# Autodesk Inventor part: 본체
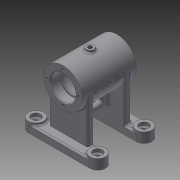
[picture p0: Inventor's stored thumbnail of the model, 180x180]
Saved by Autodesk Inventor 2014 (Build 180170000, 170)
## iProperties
Created: 2015-11
Part Number: 본체
Material: 일반
Document SubType Name: Modeling
Designer: basic
Density: 1 g/cm^3
Appearance: 기본값
Author: basic
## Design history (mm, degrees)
sketch "스케치1"
  geometry: L1 (-40, -40)-(40, -40); L2 (-40, -20)-(40, -20); A1 r 10 centre (-40, -30) between (-40, -40) and (-40, -20); A2 r 10 centre (40, -30) between (40, -40) and (40, -20); 1 further point
  constraints: 4 end point, 4 point on circle, 4 tangent, 2 centre point, 1 equal radius, 1 horizontal alignment
  dimensions: "d0" = 30 vertical distance of point (0, 0) A1.centre; "d1" = 40 horizontal distance of point (0, 0) A1.centre; "d2" = 80 distance of A2.centre A1.centre; "d3" = 20 diameter of A1
extrude "돌출1" new body sketch "스케치1" distance "d4" = 10; taper "d5" = 0 deg
sketch "스케치2"
  geometry: C1 r 10 at (-40, -30); C2 r 10 at (40, -30); A1 r 10 centre (-40, -30) between (-40, -20) and (-40, -40) reference; A2 r 10 centre (40, -30) between (40, -40) and (40, -20) reference; 1 further point
  constraints: 2 centre point, 2 coincident, 2 concentric
extrude "돌출2" join sketch "스케치2" distance "d6" = 3; taper "d7" = 0 deg
sketch "스케치3"
  geometry: C1 r 10 at (0, 0) reference; C2 r 10 at (80, 0) reference; 3 further points
  constraints: 2 coincident
hole "구멍1" sketch "스케치3" at (0, 0), (80, 0) diameter "d8" = 6; stored, may be unused: countersink angle "d12" = 90 deg, drill point angle "d14" = 118 deg; dims "d9" = 6, "d10" = 12, "d11" = 4, "d13" = 8
sketch "스케치5"
  geometry: C1 r 25 at (0, 68); 1 further point
  constraints: 1 centre point, 1 vertical alignment
  dimensions: "d19" = 68 distance of point (0, 0) C1.centre; "d20" = 50 diameter of C1
extrude "돌출4" join sketch "스케치5" stored distance "d21" = 70; taper "d22" = 0 deg
sketch "스케치6"
  geometry: L1 (80, 0)-(0, 0) reference; L2 (65, 0)-(15, 0); L3 (15, 0)-(15, 8); L4 (15, 8)-(65, 8); L5 (65, 8)-(65, 0); 2 further points
  constraints: 8 end point, 2 parallel, 1 horizontal, 1 midpoint, 1 perpendicular, 1 point on line, 1 vertical alignment
  dimensions: "d23" = 50 distance of L3.end L4.end; "d24" = 8 distance between parallel lines of L1 L4
extrude "돌출5" join sketch "스케치6" stored distance "d25" = 70; taper "d26" = 0 deg
sketch "스케치7"
  geometry: L1 (-35, 93)-(35, 93) reference; L2 (35, 93)-(35, 43) reference; L3 (35, 43)-(28, 43) reference; L4 (28, 43)-(28, 10) reference; L5 (28, 10)-(40, 10) reference; L6 (40, 10)-(40, 0) reference; L7 (40, 0)-(20, 0) reference; L8 (20, 0)-(20, 43) reference; L9 (20, 43)-(-20, 43) reference; L10 (-20, 43)-(-20, 0) reference; L11 (-20, 0)-(-40, 0) reference; L12 (-40, 0)-(-40, 10) reference; L13 (-40, 10)-(-28, 10) reference; L14 (-28, 10)-(-28, 43) reference; L15 (-28, 43)-(-35, 43) reference; L16 (-35, 43)-(-35, 93) reference; L17 (-20, 43)-(20, 43); L18 (20, 43)-(20, 23); L19 (20, 23)-(-20, 23); L20 (-20, 23)-(-20, 43); 1 further point
  constraints: 8 end point, 2 parallel, 1 horizontal, 1 perpendicular
  dimensions: "d27" = 20 distance between parallel lines of L19 L17
extrude "돌출6" join sketch "스케치7" stored distance "d28" = 8; taper "d29" = 0 deg
sketch "스케치8"
  geometry: L1 (-92.678, -35)-(-92.678, 35) reference; L2 (-92.678, 35)-(-43.322, 35) reference; L3 (-43.322, 35)-(-43.322, 28) reference; L4 (-43.322, 28)-(-10, 28) reference; L5 (-10, 28)-(-10, 40) reference; L6 (-10, 40)-(0, 40) reference; L7 (0, 40)-(0, 20) reference; L8 (0, 20)-(-23, 20) reference; L9 (-23, 20)-(-23, -20) reference; L10 (-43, -20)-(-23, -20) reference; L11 (-43, -20)-(-43, 20) reference; L12 (-43, 20)-(-43.322, 20) reference; L13 (-43.322, 20)-(-43.322, -20) reference; L14 (-43.322, -20)-(-43, -20) reference; L15 (-43.322, -35)-(-92.678, -35) reference; L16 (-43.322, -28)-(-43.322, -35) reference; L17 (-10, -28)-(-43.322, -28) reference; L18 (-10, -40)-(-10, -28) reference; L19 (0, -40)-(-10, -40) reference; L20 (0, -20)-(0, -40) reference; L21 (-23, -20)-(0, -20) reference; L22 (-23, 20)-(-43, 20) reference; L23 (-36.5, -8)-(-36.5, 8); L24 (-29.5, -8)-(-29.5, 8); A1 r 3.5 centre (-33, -8) between (-36.5, -8) and (-29.5, -8); A2 r 3.5 centre (-33, 8) between (-36.5, 8) and (-29.5, 8); 1 further point
  constraints: 4 end point, 4 point on circle, 3 tangent, 2 centre point, 1 equal radius, 1 perpendicular, 1 vertical alignment
  dimensions: "d30" = 8 vertical distance of A2.centre point (0, 0); "d31" = 16 distance of A1.centre A2.centre; "d32" = 33 distance from line of L7 A2.centre; "d33" = 7 diameter of A2
extrude "돌출7" cut sketch "스케치8" stored distance "d34" = 8; taper "d35" = 0 deg
node "작업 평면1"
sketch "스케치9"
  geometry: C1 r 5 at (40, -40); 1 further point
  constraints: 1 centre point, 1 coincident
  dimensions: "d37" = 10 diameter of C1
extrude "돌출8" join sketch "스케치9" stored distance "d38" = 8; taper "d39" = 0 deg
sketch "스케치10"
  geometry: L1 (-4, 29.5)-(4, 29.5) reference; L2 (4, 29.5)-(4, 23) reference; L3 (4, 23)-(-4, 23) reference; L4 (-4, 23)-(-4, 29.5) reference; L5 (-4, 36.5)-(-4, 43) reference; L6 (-4, 43)-(0, 43) reference; L7 (0, 43)-(4, 43) reference; L8 (4, 43)-(4, 36.5) reference; L9 (4, 36.5)-(-4, 36.5) reference; L10 (-5, 92.495)-(-5, 96) reference; L11 (-5, 96)-(5, 96) reference; L12 (5, 96)-(5, 92.495) reference; L13 (0, 68)-(0, 43); L14 (0, 68)-(12.5, 46.349); L15 (0, 68)-(14, 43.751); L16 (14, 43.751)-(19.196, 46.751); L17 (19.196, 46.751)-(17.331, 49.982); A1 r 25 centre (0, 68) between (0, 43) and (5, 92.495) reference; A2 r 25 centre (0, 68) between (-5, 92.495) and (0, 43) reference; A3 r 25 centre (0, 68) between (5, 92.495) and (0, 43); A4 r 25 centre (0, 68) between (12.5, 46.349) and (17.331, 49.982); 1 further point
  constraints: 11 end point, 6 point on circle, 3 perpendicular, 2 centre point, 1 coincident, 1 collinear, 1 point on line
  dimensions: "d41" = 30 deg angle of L14 L13; "d42" = 28 distance of L13.start L15.end; "d43" = 6 distance of L15.end L16.end
revolve "회전1" sketch "스케치10" stored, may be unused: angle "d44" = 90 deg
sketch "스케치12"
  geometry: 1 further point
sketch "스케치13"
  geometry: C1 r 25 at (0, 0) reference; C2 r 16 at (0, 0); 1 further point
  constraints: 1 centre point, 1 coincident
  dimensions: "d45" = 32 diameter of C2
extrude "돌출9" cut sketch "스케치13" distance "d46" = 12; taper "d47" = 0 deg
sketch "스케치14"
  geometry: C1 r 16 at (0, 0) reference; C2 r 14 at (0, 0); 1 further point
  constraints: 1 centre point, 1 coincident
  dimensions: "d48" = 28 diameter of C2
extrude "돌출10" cut sketch "스케치14" distance "d49" = 2; taper "d50" = 0 deg
sketch "스케치15"
  geometry: C1 r 14 at (0, 0) reference; C2 r 21 at (0, 0); 1 further point
  constraints: 1 centre point, 1 coincident
  dimensions: "d51" = 42 diameter of C2
extrude "돌출11" cut sketch "스케치15" distance "d52" = 42; taper "d53" = 0 deg
sketch "스케치16"
  geometry: C1 r 25 at (0, 0) reference; C2 r 16 at (0, 0); 1 further point
  constraints: 1 centre point, 1 coincident
  dimensions: "d54" = 32 diameter of C2
extrude "돌출12" cut sketch "스케치16" distance "d55" = 12; taper "d56" = 0 deg
sketch "스케치17"
  geometry: C1 r 16 at (0, 0) reference; C2 r 14 at (0, 0); 1 further point
  constraints: 1 centre point, 1 coincident
  dimensions: "d57" = 28 diameter of C2
extrude "돌출13" cut sketch "스케치17" distance "d58" = 2; taper "d59" = 0 deg
sketch "스케치18"
  geometry: C1 r 16 at (0, 0) reference; 2 further points
  constraints: 1 vertical alignment
  dimensions: "d60" = 20 distance of C1.centre point (0, -20)
hole "구멍2" sketch "스케치18" at (0, -20) diameter "d61" = 3.242; stored, may be unused: countersink angle "d65" = 90 deg, drill point angle "d67" = 118 deg; dims "d62" = 8, "d63" = 12, "d64" = 4, "d66" = 10
hole "구멍3" diameter "d73" = 5.188; stored, may be unused: countersink angle "d77" = 90 deg, drill point angle "d79" = 118 deg; dims "d71" = 10, "d72" = 10, "d74" = 8, "d75" = 12, "d76" = 4, "d78" = 10
hole "구멍4" diameter "d82" = 5.188; stored, may be unused: countersink angle "d86" = 90 deg, drill point angle "d88" = 0 deg; dims "d80" = 10, "d81" = 10, "d83" = 6, "d84" = 4, "d85" = 2, "d87" = 8
node "작업 평면2"
sketch "스케치19"
  geometry: L1 (-35, 25)-(35, 25) reference; 2 further points
  constraints: 1 vertical alignment, 1 other
  dimensions: "d89" = 25 distance from line of L1 point (0, 0)
feature "엠보싱1" sketch "스케치19" dims "d90" = 0.5, "d91" = 0
fillet "모깎기17" dims "d108" = 2
fillet "모깎기20" dims "d111" = 2
fillet "모깎기21" dims "d112" = 2
fillet "모깎기22" dims "d113" = 2
fillet "모깎기23" dims "d114" = 2
fillet "모깎기24" dims "d115" = 2
fillet "모깎기25" dims "d116" = 2
fillet "모깎기26" dims "d117" = 0.3
chamfer "모따기1" distance "d118" = 1; stored, may be unused: second distance "d119" = 2, angle "d120" = 45 deg
chamfer "모따기2" distance "d121" = 1; stored, may be unused: second distance "d122" = 2, angle "d123" = 45 deg
fillet "모깎기27" dims "d124" = 3
fillet "모깎기28" dims "d125" = 0.3
node "솔리드1"
mirror "대칭1"
mirror "대칭2"
pattern_circular "원형 패턴1" dims angle "d69" = 360 deg
mirror "대칭3"
node "절단 모서리 투영1"
node "절단 모서리 투영2"
node "절단 모서리 투영3"
other parameters: "d36" = -96
